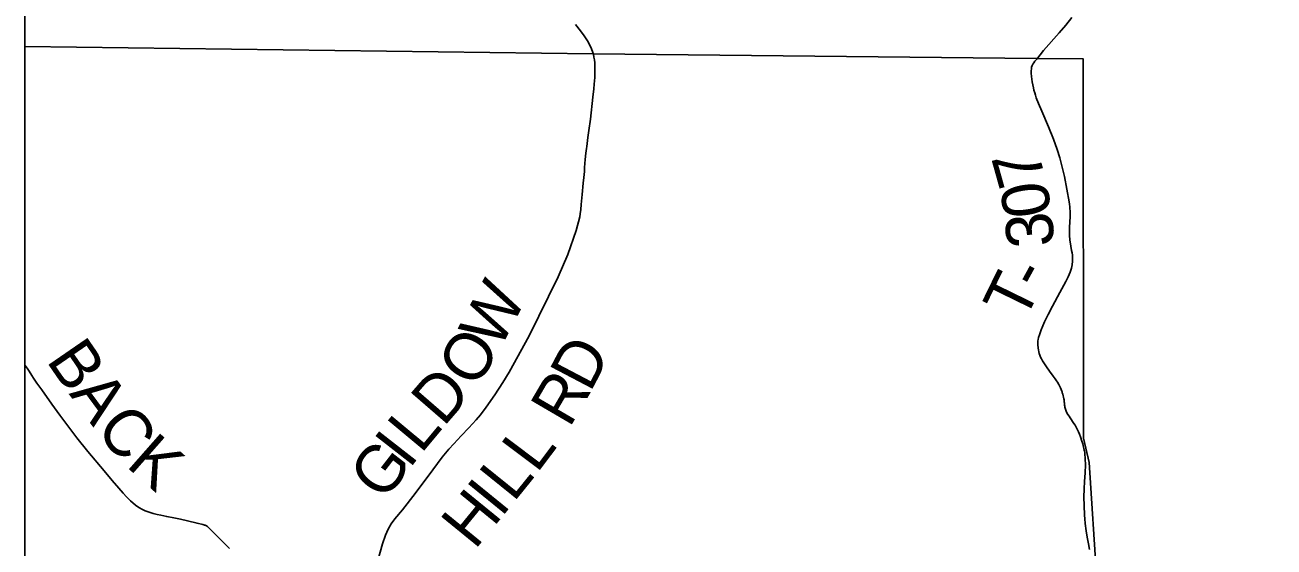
# Model space of a CAD drawing. Extents: x -10.5 to 40.6, y -3.2 to 22.
# Drawn here: x -10.544 to -9.045, y 18.823 to 19.45 of the extents above; entities that cross this region are included whole.
import ezdxf

# ---------------------------------------------------------------- set-up
doc = ezdxf.new("R2010")
doc.units = 0
for name, color, linetype in [('GM_X_Township_Road', 7, 'Continuous'), ('GM_X_Township_Road_Text', 7, 'Continuous'), ('GM_X_Township_Text', 7, 'Continuous')]:
    doc.layers.add(name, color=color, linetype=linetype)

msp = doc.modelspace()

# ---------------------------------------------------------------- linework, layer by layer
at = {"layer": 'GM_X_Township_Road'}
for points in [[(-9.2874, 19.4587), (-9.2947, 19.4494), (-9.3025, 19.4403), (-9.3213, 19.4193), (-9.3295, 19.4088)], [(-9.8619, 19.4147), (-9.8648, 19.423), (-9.8688, 19.4307), (-9.8731, 19.4369), (-9.8774, 19.4428), (-9.8834, 19.4505)], [(-10.1282, 18.7793), (-10.1152, 18.8266), (-10.1115, 18.8369), (-10.1085, 18.8441), (-10.1048, 18.8503), (-10.1005, 18.8566), (-10.0911, 18.8674), (-10.076, 18.887), (-10.0548, 18.9154), (-10.0434, 18.9305), (-10.0355, 18.9402), (-10.0294, 18.9467), (-10.0206, 18.956), (-10.0115, 18.9657), (-10.0026, 18.9753), (-9.9976, 18.9815), (-9.9908, 18.9906), (-9.9803, 19.0055), (-9.9708, 19.0202), (-9.9632, 19.0327), (-9.9389, 19.0763), (-9.9041, 19.147), (-9.8927, 19.1742), (-9.8824, 19.203), (-9.878, 19.2194), (-9.8776, 19.2228), (-9.877, 19.2282), (-9.8764, 19.2339), (-9.8754, 19.2462), (-9.8741, 19.2597), (-9.8733, 19.2665), (-9.8727, 19.2738), (-9.8724, 19.2787), (-9.8717, 19.288), (-9.871, 19.2959), (-9.8702, 19.3015), (-9.8699, 19.3039), (-9.8686, 19.3144), (-9.8675, 19.323), (-9.8655, 19.3365), (-9.8625, 19.363), (-9.8614, 19.3729), (-9.8608, 19.3787), (-9.8605, 19.3826), (-9.8603, 19.3866), (-9.8602, 19.3912), (-9.8601, 19.3962), (-9.8602, 19.4019), (-9.8603, 19.4043), (-9.8606, 19.4077), (-9.8612, 19.4113), (-9.8619, 19.4147)], [(-9.2662, 18.8197), (-9.2675, 18.8265), (-9.2689, 18.8343), (-9.2702, 18.8422), (-9.2713, 18.8508), (-9.2717, 18.8566), (-9.2721, 18.8608), (-9.2727, 18.8725), (-9.2728, 18.8825), (-9.2725, 18.8923), (-9.272, 18.9015), (-9.2714, 18.9119), (-9.2711, 18.9215), (-9.2713, 18.9287), (-9.2718, 18.9348), (-9.2719, 18.9363), (-9.2721, 18.9376), (-9.2724, 18.939), (-9.2728, 18.9409), (-9.2732, 18.9427), (-9.2743, 18.9465), (-9.2752, 18.9497), (-9.277, 18.955), (-9.2782, 18.9582), (-9.2793, 18.9608), (-9.2805, 18.9633), (-9.2817, 18.9658), (-9.2835, 18.9688), (-9.2849, 18.9711), (-9.2894, 18.9777), (-9.2906, 18.9796), (-9.2921, 18.9819), (-9.2932, 18.9838), (-9.2941, 18.9859), (-9.295, 18.9883), (-9.2956, 18.9905), (-9.2959, 18.9919), (-9.296, 18.9931), (-9.2963, 18.995), (-9.2963, 18.9959), (-9.2964, 18.9968), (-9.2965, 18.9978), (-9.2967, 18.9994), (-9.297, 19.0007), (-9.2983, 19.0061), (-9.2988, 19.0079), (-9.2991, 19.0089), (-9.2995, 19.0099), (-9.3002, 19.012), (-9.301, 19.0137), (-9.3031, 19.0179), (-9.3046, 19.0206), (-9.3058, 19.0224), (-9.3073, 19.0245), (-9.3098, 19.0279), (-9.3143, 19.0339), (-9.3179, 19.0389), (-9.3211, 19.0438), (-9.3225, 19.0461), (-9.3237, 19.0485), (-9.3249, 19.0508), (-9.3257, 19.053), (-9.3265, 19.0551), (-9.327, 19.0572), (-9.3275, 19.0594), (-9.3279, 19.0614), (-9.3284, 19.0657), (-9.3284, 19.0673), (-9.3283, 19.0688), (-9.3282, 19.0704), (-9.3279, 19.0719), (-9.3273, 19.0742), (-9.3263, 19.0777), (-9.3242, 19.0835), (-9.32, 19.0931), (-9.3157, 19.1021), (-9.3106, 19.1121), (-9.3016, 19.1284), (-9.2944, 19.1414), (-9.2918, 19.147), (-9.2895, 19.1528), (-9.2879, 19.1575), (-9.287, 19.1617), (-9.2868, 19.1629), (-9.2866, 19.165), (-9.2864, 19.1674), (-9.2864, 19.1698), (-9.2867, 19.1732), (-9.2871, 19.1759), (-9.2876, 19.1787), (-9.2894, 19.1891), (-9.2898, 19.1914), (-9.2899, 19.1934), (-9.2901, 19.1953), (-9.2902, 19.1971), (-9.2903, 19.2009), (-9.2902, 19.204), (-9.2902, 19.2064), (-9.2894, 19.2195), (-9.2894, 19.2233), (-9.2894, 19.2263), (-9.2896, 19.2288), (-9.2898, 19.2312), (-9.2902, 19.2346), (-9.2906, 19.2374), (-9.2933, 19.2527), (-9.2963, 19.2679), (-9.2988, 19.2788), (-9.3018, 19.2902), (-9.3049, 19.3003), (-9.3095, 19.3125), (-9.3155, 19.3275), (-9.3235, 19.3464), (-9.3274, 19.3554), (-9.3301, 19.3624), (-9.3311, 19.3653), (-9.332, 19.3683), (-9.3329, 19.3715), (-9.3336, 19.3742), (-9.335, 19.3814), (-9.3359, 19.388), (-9.3361, 19.3918), (-9.3361, 19.3948), (-9.336, 19.397), (-9.3357, 19.3991), (-9.335, 19.4009), (-9.3342, 19.4025), (-9.3332, 19.4042), (-9.3317, 19.4063), (-9.3295, 19.4088)], [(-10.2988, 18.8209), (-10.3142, 18.8362), (-10.3236, 18.8457), (-10.3245, 18.8465), (-10.3255, 18.8474), (-10.3264, 18.848), (-10.3272, 18.8484), (-10.328, 18.8488), (-10.329, 18.849), (-10.3299, 18.8493), (-10.3309, 18.8495), (-10.3379, 18.8512), (-10.3493, 18.854), (-10.3578, 18.8559), (-10.3657, 18.8575), (-10.3742, 18.8592), (-10.3815, 18.8608), (-10.3858, 18.8617), (-10.3906, 18.8629), (-10.3954, 18.8643), (-10.4, 18.866), (-10.4034, 18.8676), (-10.4077, 18.87), (-10.4117, 18.8729), (-10.4179, 18.8782), (-10.4227, 18.883), (-10.4265, 18.8871), (-10.4318, 18.8932), (-10.4398, 18.9026), (-10.4494, 18.9141), (-10.4689, 18.9374), (-10.4821, 18.9539), (-10.4942, 18.9696), (-10.5027, 18.9811), (-10.5121, 18.9942), (-10.5244, 19.0114), (-10.5301, 19.0195), (-10.5341, 19.0255), (-10.5361, 19.0286), (-10.5396, 19.0337), (-10.542, 19.0373), (-10.5445, 19.0411)]]:
    msp.add_lwpolyline(points, dxfattribs=at)
at = {"layer": 'GM_X_Township_Text'}
for points in [[(-6.192, 17.3965), (-6.1792, 18.1778), (-6.179, 18.1863), (-6.1678, 18.8746), (-6.1678, 18.8755), (-6.1618, 20.9), (-10.5445, 20.9), (-10.5445, 19.4241)], [(-10.5445, 19.4241), (-9.8621, 19.4152), (-9.3297, 19.4093), (-9.2736, 19.4089), (-9.2734, 18.9532), (-9.2666, 18.9242), (-9.2573, 18.7823), (-9.2552, 18.7211), (-9.2586, 18.705), (-9.2677, 18.6789), (-9.2756, 18.3974), (-9.1719, 18.3965), (-8.6421, 18.3977), (-8.2403, 18.3894), (-8.2411, 17.9704), (-8.2441, 17.4134), (-7.9861, 17.4086), (-7.6509, 17.4026), (-7.3241, 17.3974), (-6.9004, 17.4016), (-6.4692, 17.3961), (-6.192, 17.3965), (-6.1874, 16.891), (-6.062, 16.8858)], [(-10.5445, 19.4241), (-10.5445, 16.0741), (-10.3151, 16.0685), (-10.1031, 16.0664), (-9.5534, 16.0497), (-8.7017, 16.0275), (-8.5879, 16.0247), (-8.2615, 16.0223), (-8.2451, 17.3912), (-8.2441, 17.4134)]]:
    msp.add_lwpolyline(points, dxfattribs=at)

# ---------------------------------------------------------------- texts
at = {"layer": 'GM_X_Township_Road_Text'}
for s, rotation, p in [('7', 105.6764, (-9.3184, 19.2648)), ('0', 98.5311, (-9.3116, 19.2229)), ('3', 95.3688, (-9.3079, 19.185)), ('T', 63.9676, (-9.3446, 19.0917)), ('-', 61.3303, (-9.3263, 19.1292)), ('W', 62.4239, (-9.9748, 19.0582)), ('O', 58.1517, (-10.0035, 19.0117)), ('B', 304.5377, (-10.5198, 19.0467)), ('D', 62.2872, (-9.8659, 19.0072)), ('A', 306.3158, (-10.4922, 19.0067)), ('D', 49.1043, (-10.042, 18.966)), ('R', 59.6788, (-9.8908, 18.9645)), ('C', 308.7513, (-10.461, 18.9643)), ('L', 50.2136, (-10.069, 18.9336)), ('I', 52.0216, (-10.0831, 18.9155)), ('K', 318.6656, (-10.4244, 18.9202)), ('G', 52.2209, (-10.1137, 18.8761)), ('L', 53.0507, (-9.9299, 18.9101)), ('L', 51.1093, (-9.9579, 18.8753)), ('I', 50.8636, (-9.9727, 18.857)), ('H', 50.8003, (-10.0044, 18.8182))]:
    msp.add_text(s, height=0.0568, rotation=rotation, dxfattribs=at).set_placement(p)

doc.saveas('drawing.dxf')
